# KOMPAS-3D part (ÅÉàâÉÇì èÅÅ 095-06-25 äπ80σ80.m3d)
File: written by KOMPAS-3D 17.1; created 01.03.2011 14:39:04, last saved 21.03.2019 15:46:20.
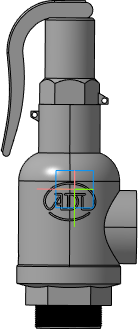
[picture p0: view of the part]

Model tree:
1. Операция без истории:1

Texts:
  Viktor2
